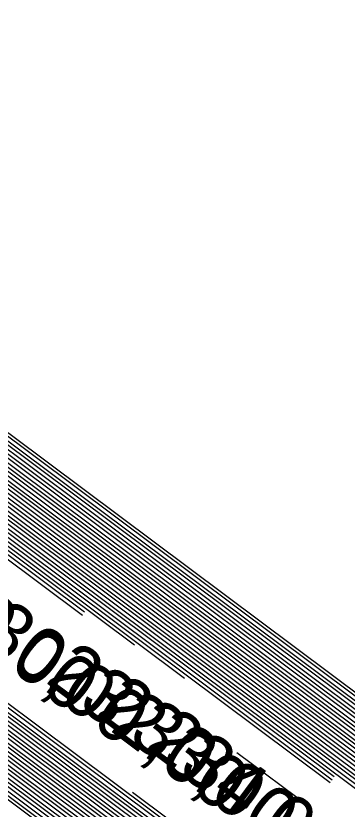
# Model space of a CAD drawing. Extents: x -500397 to -496810, y -1135552 to -1132176.
# Drawn here: x -500216.69 to -500204.48, y -1134856.03 to -1134826.78 of the extents above; entities that cross this region are included whole.
import ezdxf

# ---------------------------------------------------------------- set-up
doc = ezdxf.new("R2010")
doc.units = 0
doc.layers.add('30', color=7, linetype='Continuous')
doc.layers.add('40', color=7, linetype='Continuous')

msp = doc.modelspace()

# ---------------------------------------------------------------- linework, layer by layer
at = {"layer": '30'}
for points in [[(-500247.601, -1134824.58), (-500240.317, -1134829.167), (-500238.508, -1134830.331), (-500236.723, -1134831.53), (-500234.963, -1134832.766), (-500233.228, -1134834.036), (-500205.109, -1134855.056)], [(-500247.001, -1134824.872), (-500239.688, -1134829.477), (-500237.872, -1134830.646), (-500236.08, -1134831.85), (-500234.313, -1134833.09), (-500232.571, -1134834.366), (-500205.031, -1134854.953)], [(-500204.954, -1134854.849), (-500231.914, -1134834.696), (-500233.663, -1134833.415), (-500235.437, -1134832.17), (-500237.236, -1134830.96), (-500239.059, -1134829.787), (-500246.402, -1134825.164)], [(-500245.802, -1134825.456), (-500238.431, -1134830.097), (-500236.6, -1134831.275), (-500234.794, -1134832.489), (-500233.013, -1134833.739), (-500231.257, -1134835.025), (-500199.584, -1134858.702)], [(-500199.507, -1134858.598), (-500230.6, -1134835.355), (-500232.363, -1134834.064), (-500234.151, -1134832.809), (-500235.964, -1134831.59), (-500237.802, -1134830.407), (-500245.203, -1134825.748)], [(-500199.429, -1134858.495), (-500229.943, -1134835.685), (-500231.713, -1134834.389), (-500233.508, -1134833.129), (-500235.329, -1134831.905), (-500237.174, -1134830.717), (-500244.603, -1134826.04)], [(-500166.359, -1134880.471), (-500218.774, -1134841.289), (-500220.663, -1134839.907), (-500222.578, -1134838.563), (-500224.519, -1134837.257), (-500226.487, -1134835.991), (-500234.412, -1134831.001), (-500236.393, -1134829.753), (-500238.373, -1134828.504), (-500240.352, -1134827.253), (-500242.331, -1134826.002)], [(-500244.004, -1134826.331), (-500236.545, -1134831.028), (-500234.693, -1134832.22), (-500232.866, -1134833.448), (-500231.063, -1134834.713), (-500229.286, -1134836.014), (-500197.588, -1134859.71)], [(-500241.761, -1134826.275), (-500239.775, -1134827.531), (-500237.788, -1134828.786), (-500235.801, -1134830.04), (-500233.813, -1134831.293), (-500225.859, -1134836.301), (-500223.883, -1134837.572), (-500221.935, -1134838.882), (-500220.013, -1134840.231), (-500218.117, -1134841.619), (-500166.281, -1134880.368)], [(-500243.404, -1134826.623), (-500235.916, -1134831.338), (-500234.057, -1134832.535), (-500232.223, -1134833.768), (-500230.413, -1134835.038), (-500228.629, -1134836.344), (-500186.925, -1134867.519)], [(-500173.648, -1134875.507), (-500220.745, -1134840.3), (-500222.613, -1134838.933), (-500224.507, -1134837.604), (-500226.427, -1134836.313), (-500228.373, -1134835.06), (-500236.211, -1134830.125), (-500238.17, -1134828.891), (-500240.128, -1134827.656), (-500242.085, -1134826.419)], [(-500171.806, -1134876.722), (-500220.088, -1134840.63), (-500221.963, -1134839.257), (-500223.864, -1134837.923), (-500225.791, -1134836.628), (-500227.744, -1134835.37), (-500235.611, -1134830.417), (-500237.577, -1134829.178), (-500239.543, -1134827.938), (-500241.508, -1134826.697)], [(-500164.44, -1134881.583), (-500217.46, -1134841.948), (-500219.363, -1134840.556), (-500221.292, -1134839.202), (-500223.247, -1134837.887), (-500225.23, -1134836.611), (-500233.213, -1134831.585), (-500235.209, -1134830.327), (-500237.203, -1134829.069), (-500239.197, -1134827.809), (-500241.19, -1134826.549)], [(-500186.848, -1134867.415), (-500227.972, -1134836.674), (-500229.763, -1134835.362), (-500231.58, -1134834.088), (-500233.421, -1134832.85), (-500235.288, -1134831.648), (-500242.805, -1134826.915)], [(-500186.538, -1134867.001), (-500225.344, -1134837.992), (-500227.163, -1134836.661), (-500229.008, -1134835.366), (-500230.878, -1134834.109), (-500232.773, -1134832.889), (-500240.407, -1134828.083), (-500242.315, -1134826.88)], [(-500177.408, -1134873.18), (-500222.716, -1134839.311), (-500224.563, -1134837.959), (-500226.436, -1134836.645), (-500228.334, -1134835.368), (-500230.259, -1134834.129), (-500238.009, -1134829.25), (-500239.946, -1134828.029), (-500241.883, -1134826.808)], [(-500240.93, -1134826.975), (-500238.958, -1134828.221), (-500236.985, -1134829.466), (-500235.012, -1134830.709), (-500227.116, -1134835.68), (-500225.155, -1134836.942), (-500223.221, -1134838.243), (-500221.313, -1134839.582), (-500219.431, -1134840.959), (-500166.436, -1134880.575)], [(-500240.62, -1134826.822), (-500238.619, -1134828.087), (-500236.618, -1134829.352), (-500234.616, -1134830.615), (-500232.614, -1134831.876), (-500224.601, -1134836.921), (-500222.612, -1134838.202), (-500220.649, -1134839.522), (-500218.713, -1134840.88), (-500216.803, -1134842.278), (-500160.834, -1134884.117)], [(-500186.771, -1134867.312), (-500227.315, -1134837.003), (-500229.113, -1134835.687), (-500230.937, -1134834.407), (-500232.785, -1134833.164), (-500234.659, -1134831.958), (-500242.205, -1134827.207)], [(-500184.697, -1134868.216), (-500224.687, -1134838.322), (-500226.513, -1134836.985), (-500228.365, -1134835.686), (-500230.242, -1134834.424), (-500232.145, -1134833.199), (-500239.807, -1134828.374), (-500241.723, -1134827.168)], [(-500241.298, -1134827.09), (-500239.354, -1134828.317), (-500237.409, -1134829.542), (-500229.63, -1134834.44), (-500227.698, -1134835.683), (-500225.793, -1134836.964), (-500223.913, -1134838.284), (-500222.059, -1134839.641), (-500177.331, -1134873.077)], [(-500066.515, -1134969.857), (-500057.168, -1134975.125), (-500055.988, -1134975.765), (-500055.565, -1134975.931), (-500055.898, -1134975.622), (-500056.987, -1134974.837), (-500063.092, -1134970.588), (-500064.595, -1134969.533), (-500066.088, -1134968.465), (-500067.572, -1134967.385), (-500069.047, -1134966.292), (-500254.751, -1134827.472)], [(-500254.674, -1134827.368), (-500067.327, -1134967.416), (-500065.844, -1134968.515), (-500064.353, -1134969.601), (-500062.852, -1134970.674), (-500061.342, -1134971.734), (-500055.205, -1134976.006), (-500054.109, -1134976.794), (-500053.775, -1134977.105), (-500054.2, -1134976.939), (-500055.386, -1134976.295), (-500064.782, -1134971)], [(-500241.606, -1134827.499), (-500234.031, -1134832.268), (-500232.149, -1134833.479), (-500230.294, -1134834.727), (-500228.463, -1134836.012), (-500226.658, -1134837.333), (-500186.693, -1134867.208)], [(-500241.13, -1134827.455), (-500239.208, -1134828.666), (-500231.516, -1134833.509), (-500229.606, -1134834.739), (-500227.722, -1134836.005), (-500225.863, -1134837.31), (-500224.03, -1134838.652), (-500177.563, -1134873.387)], [(-500240.713, -1134827.373), (-500238.762, -1134828.604), (-500236.81, -1134829.834), (-500229.002, -1134834.75), (-500227.063, -1134835.998), (-500225.15, -1134837.284), (-500223.263, -1134838.608), (-500221.402, -1134839.97), (-500173.725, -1134875.611)], [(-500186.616, -1134867.104), (-500226.001, -1134837.663), (-500227.813, -1134836.336), (-500229.651, -1134835.047), (-500231.514, -1134833.794), (-500233.402, -1134832.579), (-500241.006, -1134827.791)], [(-500240.538, -1134827.742), (-500238.608, -1134828.958), (-500230.887, -1134833.819), (-500228.97, -1134835.053), (-500227.079, -1134836.325), (-500225.213, -1134837.634), (-500223.373, -1134838.981), (-500177.486, -1134873.284)], [(-500214.161, -1134848.773), (-500235.199, -1134833.047), (-500236.913, -1134831.792), (-500238.652, -1134830.572), (-500240.415, -1134829.386), (-500242.202, -1134828.236)], [(-500212.32, -1134849.988), (-500234.542, -1134833.377), (-500236.263, -1134832.117), (-500238.009, -1134830.891), (-500239.78, -1134829.701), (-500241.574, -1134828.546)], [(-500240.945, -1134828.856), (-500239.144, -1134830.016), (-500237.366, -1134831.211), (-500235.613, -1134832.441), (-500233.885, -1134833.707), (-500210.478, -1134851.204)], [(-500241.051, -1134829.071), (-500239.295, -1134830.252), (-500237.563, -1134831.467), (-500235.856, -1134832.718), (-500214.239, -1134848.877)], [(-500251.07, -1134829.901), (-500065.608, -1134968.54), (-500064.117, -1134969.644), (-500062.618, -1134970.736), (-500061.109, -1134971.815), (-500059.591, -1134972.881), (-500053.422, -1134977.175), (-500052.321, -1134977.967), (-500051.984, -1134978.28), (-500052.412, -1134978.112), (-500053.604, -1134977.465), (-500063.049, -1134972.142)], [(-500061.316, -1134973.285), (-500051.822, -1134978.635), (-500050.624, -1134979.286), (-500050.194, -1134979.454), (-500050.533, -1134979.14), (-500051.639, -1134978.343), (-500057.84, -1134974.027), (-500059.366, -1134972.956), (-500060.883, -1134971.871), (-500062.39, -1134970.774), (-500063.888, -1134969.664), (-500249.228, -1134831.116)], [(-500247.309, -1134832.228), (-500060.449, -1134971.912), (-500058.936, -1134973.033), (-500057.413, -1134974.142), (-500055.881, -1134975.238), (-500054.339, -1134976.32), (-500048.074, -1134980.681), (-500046.956, -1134981.485), (-500046.614, -1134981.803), (-500047.049, -1134981.633), (-500048.259, -1134980.976), (-500057.851, -1134975.57)], [(-500247.387, -1134832.331), (-500062.169, -1134970.788), (-500060.663, -1134971.904), (-500059.148, -1134973.007), (-500057.623, -1134974.097), (-500056.09, -1134975.174), (-500049.857, -1134979.512), (-500048.744, -1134980.313), (-500048.404, -1134980.628), (-500048.836, -1134980.459), (-500050.041, -1134979.805), (-500059.584, -1134974.428)], [(-500056.118, -1134976.713), (-500046.477, -1134982.146), (-500045.261, -1134982.806), (-500044.824, -1134982.977), (-500045.168, -1134982.658), (-500046.291, -1134981.849), (-500052.588, -1134977.467), (-500054.138, -1134976.378), (-500055.678, -1134975.277), (-500057.208, -1134974.163), (-500058.73, -1134973.036), (-500243.703, -1134834.762)], [(-500054.385, -1134977.855), (-500044.696, -1134983.316), (-500043.473, -1134983.98), (-500043.034, -1134984.152), (-500043.379, -1134983.831), (-500044.509, -1134983.018), (-500050.838, -1134978.613), (-500052.395, -1134977.519), (-500053.943, -1134976.413), (-500055.481, -1134975.293), (-500057.01, -1134974.16), (-500241.862, -1134835.977)], [(-500047.454, -1134982.426), (-500037.569, -1134987.997), (-500036.321, -1134988.674), (-500035.874, -1134988.849), (-500036.226, -1134988.522), (-500037.378, -1134987.693), (-500043.835, -1134983.199), (-500045.424, -1134982.083), (-500047.003, -1134980.954), (-500048.572, -1134979.811), (-500050.132, -1134978.656), (-500239.788, -1134836.881)], [(-500045.722, -1134983.568), (-500035.787, -1134989.167), (-500034.533, -1134989.848), (-500034.084, -1134990.024), (-500034.438, -1134989.695), (-500035.596, -1134988.862), (-500042.084, -1134984.345), (-500043.681, -1134983.224), (-500045.268, -1134982.089), (-500046.845, -1134980.941), (-500048.413, -1134979.78), (-500239.711, -1134836.778)], [(-500239.633, -1134836.674), (-500046.693, -1134980.903), (-500045.118, -1134982.071), (-500043.533, -1134983.224), (-500041.938, -1134984.365), (-500040.334, -1134985.492), (-500033.813, -1134990.03), (-500032.649, -1134990.868), (-500032.294, -1134991.198), (-500032.746, -1134991.021), (-500034.006, -1134990.337), (-500043.989, -1134984.711)], [(-500240.02, -1134837.192), (-500055.291, -1134975.284), (-500053.754, -1134976.422), (-500052.208, -1134977.548), (-500050.652, -1134978.66), (-500049.087, -1134979.759), (-500042.726, -1134984.187), (-500041.591, -1134985.004), (-500041.244, -1134985.326), (-500041.685, -1134985.153), (-500042.914, -1134984.486), (-500052.653, -1134978.998)], [(-500050.92, -1134980.141), (-500041.132, -1134985.656), (-500039.897, -1134986.327), (-500039.454, -1134986.5), (-500039.803, -1134986.177), (-500040.943, -1134985.355), (-500047.336, -1134980.906), (-500048.909, -1134979.801), (-500050.473, -1134978.683), (-500052.027, -1134977.552), (-500053.571, -1134976.408), (-500239.943, -1134837.088)], [(-500049.187, -1134981.283), (-500039.351, -1134986.826), (-500038.109, -1134987.5), (-500037.664, -1134987.675), (-500038.014, -1134987.349), (-500039.161, -1134986.524), (-500045.586, -1134982.052), (-500047.166, -1134980.942), (-500048.738, -1134979.819), (-500050.299, -1134978.682), (-500051.852, -1134977.532), (-500239.866, -1134836.985)], [(-500042.256, -1134985.854), (-500032.224, -1134991.507), (-500030.958, -1134992.195), (-500030.503, -1134992.372), (-500030.861, -1134992.04), (-500032.03, -1134991.199), (-500038.583, -1134986.638), (-500040.195, -1134985.506), (-500041.798, -1134984.36), (-500043.391, -1134983.2), (-500044.974, -1134982.027), (-500228.971, -1134844.483)], [(-500040.523, -1134986.996), (-500030.442, -1134992.677), (-500029.17, -1134993.368), (-500028.713, -1134993.547), (-500029.073, -1134993.213), (-500030.248, -1134992.368), (-500036.832, -1134987.784), (-500038.452, -1134986.647), (-500040.063, -1134985.495), (-500041.663, -1134984.33), (-500043.254, -1134983.151), (-500227.13, -1134845.698)], [(-500227.052, -1134845.595), (-500041.535, -1134984.275), (-500039.936, -1134985.46), (-500038.328, -1134986.63), (-500036.71, -1134987.787), (-500035.082, -1134988.931), (-500028.465, -1134993.536), (-500027.284, -1134994.386), (-500026.923, -1134994.721), (-500027.382, -1134994.542), (-500028.661, -1134993.848), (-500038.791, -1134988.139)], [(-500037.058, -1134989.281), (-500026.879, -1134995.018), (-500025.594, -1134995.715), (-500025.133, -1134995.896), (-500025.496, -1134995.559), (-500026.682, -1134994.705), (-500033.331, -1134990.077), (-500034.967, -1134988.928), (-500036.593, -1134987.766), (-500038.209, -1134986.589), (-500039.815, -1134985.399), (-500226.975, -1134845.491)], [(-500028.394, -1134994.994), (-500017.97, -1135000.869), (-500016.655, -1135001.583), (-500016.183, -1135001.768), (-500016.554, -1135001.423), (-500017.769, -1135000.548), (-500024.578, -1134995.809), (-500026.253, -1134994.633), (-500027.918, -1134993.442), (-500029.573, -1134992.238), (-500031.218, -1134991.019), (-500221.295, -1134848.929)], [(-500221.45, -1134849.137), (-500034.657, -1134988.771), (-500033.027, -1134989.978), (-500031.388, -1134991.172), (-500029.738, -1134992.351), (-500028.079, -1134993.517), (-500021.335, -1134998.211), (-500020.131, -1134999.077), (-500019.763, -1134999.419), (-500020.231, -1134999.236), (-500021.534, -1134998.528), (-500031.86, -1134992.709)], [(-500030.127, -1134993.852), (-500019.752, -1134999.698), (-500018.443, -1135000.409), (-500017.973, -1135000.593), (-500018.343, -1135000.25), (-500019.552, -1134999.38), (-500026.328, -1134994.663), (-500027.996, -1134993.492), (-500029.653, -1134992.307), (-500031.3, -1134991.108), (-500032.937, -1134989.895), (-500221.373, -1134849.033)], [(-500035.325, -1134990.424), (-500025.097, -1134996.188), (-500023.806, -1134996.889), (-500023.343, -1134997.07), (-500023.708, -1134996.732), (-500024.9, -1134995.874), (-500031.58, -1134991.224), (-500033.224, -1134990.069), (-500034.858, -1134988.901), (-500036.482, -1134987.719), (-500038.096, -1134986.523), (-500221.605, -1134849.344)], [(-500033.592, -1134991.567), (-500023.315, -1134997.358), (-500022.018, -1134998.062), (-500021.553, -1134998.244), (-500021.919, -1134997.904), (-500023.117, -1134997.042), (-500029.83, -1134992.37), (-500031.481, -1134991.21), (-500033.123, -1134990.036), (-500034.755, -1134988.849), (-500036.376, -1134987.647), (-500221.528, -1134849.24)], [(-500208.543, -1134853.942), (-500205.805, -1134855.988)], [(-500026.661, -1134996.137), (-500016.189, -1135002.039), (-500014.867, -1135002.756), (-500014.393, -1135002.942), (-500014.766, -1135002.596), (-500015.987, -1135001.717), (-500022.827, -1134996.956), (-500024.51, -1134995.774), (-500026.183, -1134994.578), (-500027.846, -1134993.367), (-500029.498, -1134992.143), (-500212.397, -1134855.42)]]:
    msp.add_lwpolyline(points, dxfattribs=at)

# ---------------------------------------------------------------- texts
at = {"layer": '40'}
for s, p in [('229,00', (-500221.176, -1134847.684)), ('230,00', (-500219.335, -1134848.899)), ('232,00', (-500215.651, -1134851.33)), ('233,00', (-500213.81, -1134852.545)), ('234,00', (-500211.968, -1134853.76))]:
    msp.add_text(s, height=2, rotation=323.2207, dxfattribs=at).set_placement(p)

doc.saveas('drawing.dxf')
